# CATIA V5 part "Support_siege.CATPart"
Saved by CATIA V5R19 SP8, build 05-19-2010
Part number: Support_siege
Bounding box of the stored display mesh (mm): x -100 to 100, y -99.803 to 324.818, z 150 to 420
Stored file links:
  G:\EU_thinkMotion\CFAO_2010\MMS_groupe2\MMS_groupe2\OK\nrosalie\nrosalie_cfao_support_d_arme_legere_final\Support_siege.CATPart
  G:\EU_thinkMotion\CFAO_2010\MMS_groupe2\MMS_groupe2\OK\nrosalie\nrosalie_cfao_support_d_arme_legere_final\nrosalie_Support_d_arme_legere.CATProduct
  G:\EU_thinkMotion\CFAO_2010\MMS_groupe2\MMS_groupe2\OK\nrosalie\nrosalie_cfao_support_d_arme_legere_final\Squelette_Colone.CATPart
  G:\EU_thinkMotion\CFAO_2010\MMS_groupe2\MMS_groupe2\OK\nrosalie\nrosalie_cfao_support_d_arme_legere_final\Colonne.CATPart
  G:\EU_thinkMotion\CFAO_2010\MMS_groupe2\MMS_groupe2\OK\nrosalie\nrosalie_cfao_support_d_arme_legere_final\6024_2Z_PART2.CATPart
  G:\EU_thinkMotion\CFAO_2010\MMS_groupe2\MMS_groupe2\OK\nrosalie\nrosalie_cfao_support_d_arme_legere_final\6020_2Z_PART2.CATPart
  G:\EU_thinkMotion\CFAO_2010\MMS_groupe2\MMS_groupe2\OK\nrosalie\nrosalie_cfao_support_d_arme_legere_final\Axe_siege.CATPart
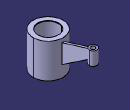
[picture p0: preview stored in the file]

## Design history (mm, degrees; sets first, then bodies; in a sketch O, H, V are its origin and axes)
Set1
  Sketch1 on Plane1, origin (0, 0, 250), H (1, 0, 0), V (0, 1, 0)
    circle A1 centre (0, 0) radius 100
    circle A2 centre (0, 0) radius 69
    reference projected circle E1 centre (0, 0) radius 69 from edge of DatumCurve2
    radius A1 = 100
    coincidence: A2 E1
Set2
  Plane1 "Plan_median_horizontal_liaison_pivot_siege": linked copy from another document
  DatumCurve1: linked copy from another document
  DatumCurve2: linked copy from another document
  Plane2 "Plan_inferieur_liaison_pivot_siege": linked copy from another document
  DatumSurface1: linked copy from another document
  DatumCurve3: linked copy from another document
  DatumCurve4: linked copy from another document
  Line1 "Axe_siege": linked copy from another document
  Plane3 "Plan_hauteur_assise_du_siege": linked copy from another document
  DatumCurve5: linked copy from another document
  DatumSurface2: linked copy from another document
  DatumSurface3: linked copy from another document
  Plane4 "Plan_superieur_liaison_pivot_siege": linked copy from another document
  Line2 "Axe_vertical_colonne": linked copy from another document
Body1 (main body)
  Pad1: profile Sketch1, direction (0, 0, 1), up to Plane2, opposite side up to face of DatumSurface1
  Sketch2 on end face of Pad1, origin (0, 0, 150), H (1, 0, 0), V (0, -1, 0)
    circle A1 centre (0, 0) radius 90
    reference projected circle E1 centre (0, 0) radius 90 from edge of DatumCurve3
    coincidence: A1 E1
  Pocket1: profile Sketch2, direction (0, 0, 1), up to face of DatumSurface1, offset 5
  Sketch3 on start face of Pad1, origin (0, 0, 374), H (1, 0, 0), V (0, 1, 0)
    circle A1 centre (0, 0) radius 100
    circle A2 centre (0, 0) radius 69
    reference projected circle E1 centre (0, 0) radius 100 from edge [face of Pad1 from Sketch1.A1 | start face of Pad1]
    reference projected circle E2 centre (0, 0) radius 69 from edge of DatumCurve4
    coincidence: A1 E1, A2 E2
  Pad2: profile Sketch3, direction (0, 0, 1), length 5
  Sketch4 on Plane3, origin (0, 0, 500), H (1, 0, 0), V (0, 1, 0)
    circle A1 centre (0, 300) radius 15
    circle A2 centre (0, 300) radius 25
    reference projected circle E1 centre (0, 300) radius 15 from edge of DatumCurve5
    distance A2 A1 = 10
    coincidence: A1 E1
    concentricity: A2 A1
  Pad3: profile Sketch4, direction (0, 0, 1), up to face of DatumSurface2, offset -30, opposite side up to face of DatumSurface3, offset -70
  Sketch5 on yz-plane, origin (0, 0, 0), H (0, 1, 0), V (0, 0, 1)
    line L1 (90, 350) -> (283, 410)
    line L2 (283, 350) -> (90, 220)
    line L3 (283, 410) -> (283, 350)
    point P1 (283, 410)
    point P2 (283, 350)
    reference projected line E1 (-325, 330) -> (-275, 330) from edge [end face of Pad3 | face of Pad3 from Sketch4.A2]
    reference projected line E2 (300, 400) -> (300, 800) from Line1
    line L4 (90, 350) -> (90, 220)
    point P3 (90, 350)
    point P4 (90, 220)
    reference intersected line E3 through (0, 150) direction (-1, 0) from Plane2
    reference intersected line E4 through (0, 350) direction (-1, 0) from Plane4
    reference projected line E5 (0, 0) -> (0, 1000) from Line2
    reference intersected line E6 through (0, 420) direction (-1, 0) from start face of Pad3
    distance E1 P2 = 20
    distance L3 E2 = 17
    distance P4 E3 = 70
    distance L4 E5 = 90
    distance P1 E6 = 10
    vertical: L4 V
    coincidence: P3 E4
  Pad4: profile Sketch5, direction (1, 0, 0), length 7.5, mirrored extent
  Plane5: type Offset, RefPlane DatumSurface1, Offset 0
